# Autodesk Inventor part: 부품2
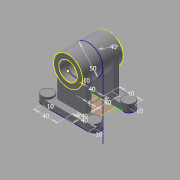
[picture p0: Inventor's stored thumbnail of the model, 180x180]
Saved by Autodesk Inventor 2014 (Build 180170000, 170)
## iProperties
Created: 2015-11
Part Number: 부품2
Material: 일반
Document SubType Name: Modeling
Designer: Owner
Density: 1 g/cm^3
Appearance: 기본값
Author: Owner
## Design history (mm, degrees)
sketch "스케치1"
  geometry: C1 r 25 at (0, 0); 1 further point
  constraints: 1 centre point, 1 coincident
  dimensions: "d1" = 50 diameter of C1
extrude "돌출1" new body sketch "스케치1" stored distance "d2" = 70; taper "d3" = 0 deg
sketch "스케치2"
  geometry: C1 r 25 at (0, 0) reference; C2 r 16 at (0, 0)
  constraints: 1 centre point, 1 coincident
  dimensions: "d4" = 32 diameter of C2
extrude "돌출2" cut sketch "스케치2" distance "d5" = 12; taper "d6" = 0 deg
sketch "스케치3"
  geometry: C1 r 25 at (0, 0) reference; C2 r 16 at (0, 0)
  constraints: 1 centre point, 1 coincident
  dimensions: "d7" = 32 diameter of C2
extrude "돌출3" cut sketch "스케치3" distance "d8" = 12; taper "d9" = 0 deg
sketch "스케치4"
  geometry: C1 r 16 at (0, 0) reference; C2 r 14 at (0, 0)
  constraints: 1 centre point, 1 coincident
  dimensions: "d10" = 28 diameter of C2
extrude "돌출4" cut sketch "스케치4" stored distance "d11" = 12; taper "d12" = 0 deg
node "작업 평면1"
sketch "스케치6"
  geometry: L1 (0, 0)-(0, 40); L2 (0, 0)-(0, -40); L3 (0, 40)-(-40, 40); L4 (-40, 40)-(0, 40); L5 (0, 40)-(40, 40); L6 (0, -40)-(-40, -40); L7 (0, -40)-(40, -40); L8 (-40, 40)-(-40, 30); L9 (-40, -40)-(-40, -30); L10 (40, -40)-(40, -30); L11 (40, 40)-(40, 30); L12 (-40, 20)-(40, 20); L13 (-40, -20)-(40, -20); L14 (0, -20)-(4, -20); L15 (0, 20)-(0, 28); L16 (0, -20)-(0, -28); A1 r 10 centre (-40, 30) between (-40, 40) and (-40, 20); A2 r 10 centre (-40, -30) between (-40, -40) and (-40, -20); A3 r 10 centre (40, -30) between (40, -40) and (40, -20); A4 r 10 centre (40, 30) between (40, 40) and (40, 20)
  constraints: 32 end point, 8 equal length, 8 point on circle, 4 centre point, 4 coincident, 3 point on line, 2 midpoint, 2 perpendicular, 2 tangent, 1 vertical
  dimensions: "d14" = 40 distance of L1.start L1.end; "d15" = 40 distance of L1.start L2.end; "d16" = 40 distance of L1.end L3.end; "d17" = 40 distance of L1.end L5.end; "d18" = 40 distance of L2.end L6.end; "d19" = 40 distance of L2.end L7.end; "d20" = 10 distance of L3.end L8.end; "d21" = 10 distance of L6.end L9.end; "d24" = 10 distance of L7.end L10.end; "d25" = 10 distance of L5.end L11.end; "d27" = 4 distance of L14.start L14.end; "d32" = 8 distance of L15.start L15.end; "d33" = 8 distance of L14.start L16.end
extrude "돌출5" join sketch "스케치6" distance "d28" = 13; taper "d29" = 0 deg
extrude "돌출6" join sketch "스케치6" distance "d30" = 10; taper "d31" = 0 deg
sketch "스케치7"
  geometry: C1 r 16 at (0, 0) reference; C2 r 25 at (0, 0) reference
sketch "스케치8"
  geometry: L1 (0, -25)-(108.525, -25); L2 (0, 25)-(113.838, 25); C1 r 16 at (0, 0) reference; A1 r 25 centre (0, 0) between (0, -25) and (0, 25) reference; 1 further point
  constraints: 4 end point, 2 point on circle, 2 tangent, 1 horizontal, 1 parallel
  node "투영된 루프1"
sketch "스케치10"
  geometry: 1 further point
sketch "스케치11"
  geometry: L1 (-3.559, 0)-(-28.559, 0); L2 (0, 20)-(0, 28); L3 (0, 28)-(-25, 28); L4 (-25, 28)-(-25, 20); L5 (0, 28)-(25, 28); L6 (25, 28)-(25, 20); L7 (25, 20)-(-25, 20); L8 (0, -20)-(0, -28); L9 (0, -28)-(-25, -28); L10 (0, -28)-(25, -28); L11 (25, -28)-(25, -20); L12 (25, -20)-(-25, -20); L13 (-25, -20)-(-25, -28); 1 further point
  constraints: 26 end point, 7 perpendicular, 4 parallel, 1 collinear, 1 horizontal
  dimensions: "d34" = 25 distance of L1.start L1.end; "d35" = 8 distance of L2.start L2.end; "d36" = 25 distance of L2.end L3.end; "d37" = 25 distance of L2.end L5.end; "d38" = 8 distance of L8.start L8.end; "d39" = 25 distance of L8.end L9.end; "d40" = 25 distance of L8.end L10.end
extrude "돌출7" join sketch "스케치11" stored distance "d41" = 10; taper "d42" = 0 deg
sketch "스케치12"
  geometry: C1 r 16 at (0, 0) reference; C2 r 25 at (0, 0) reference; A1 r 20 centre (0, 0) between (0, 20) and (-20, 0); 2 further points
  constraints: 4 point on circle, 1 centre point, 1 coincident
  dimensions: "d43" = 40 diameter of A1
node "솔리드1"
other parameters: "d13" = 68
